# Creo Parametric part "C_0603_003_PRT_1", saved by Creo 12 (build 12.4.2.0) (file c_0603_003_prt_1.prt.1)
Units: Custom; MM, KILOGRAM, SECS

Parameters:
  PTC_WM_ITERATION = "0"
  PTC_WM_VERSION = "-.0"
  PTC_WM_LIFECYCLE_STATE = "In Work"
  PTC_WM_LIFECYCLE = "MO_CADDocument"
  PTC_WM_CREATED_BY = "Maximilian Roepper (Z0017RMS: MO)"
  PTC_WM_CREATED_ON = "18-Sep-26 11:36:42 AM"
  PTC_WM_MODIFIED_BY = "Maximilian Roepper (Z0017RMS: MO)"
  PTC_WM_MODIFIED_ON = "18-Sep-26 11:36:46 AM"
  PDMLINKNUMBER = "PDM000071455101"
  PTC_WM_NAME = "c_0603_003_prt_1.prt"
  PTC_WM_NUMBER = "PDM000071455101"

Other parameters: WEIGHT, WEIGHT_FACTOR, WEIGHT_ADD, _MASS_TEMP, _DIFF_TEMP, MC_ERRORS, SUPPLIER

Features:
  1. coordinate system
  2. datum plane "PRT_YZ"
  3. datum plane "PRT_XY"
  4. datum plane "PRT_XZ"
  5. coordinate system
  6. datum axis
  7. datum axis
  8. datum axis
  9. coordinate system
  10. imported feature
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
Other named items: PRT, SIEMENS_MO, DRW_VIEW_ORG, PRT_X, PRT_Y, PRT_Z, CS0, ROUGH_GROB

Layers: 00_STD_CSYS-KSYS, 01_STD_PLANES-EBENEN, 02_STD_AXES-ACHSEN, 03_STD_CSYS-KSYS, 24_IMPORT_FEAT-IMPORT_KE

Surfaces: 16 plane, 12 cylinder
